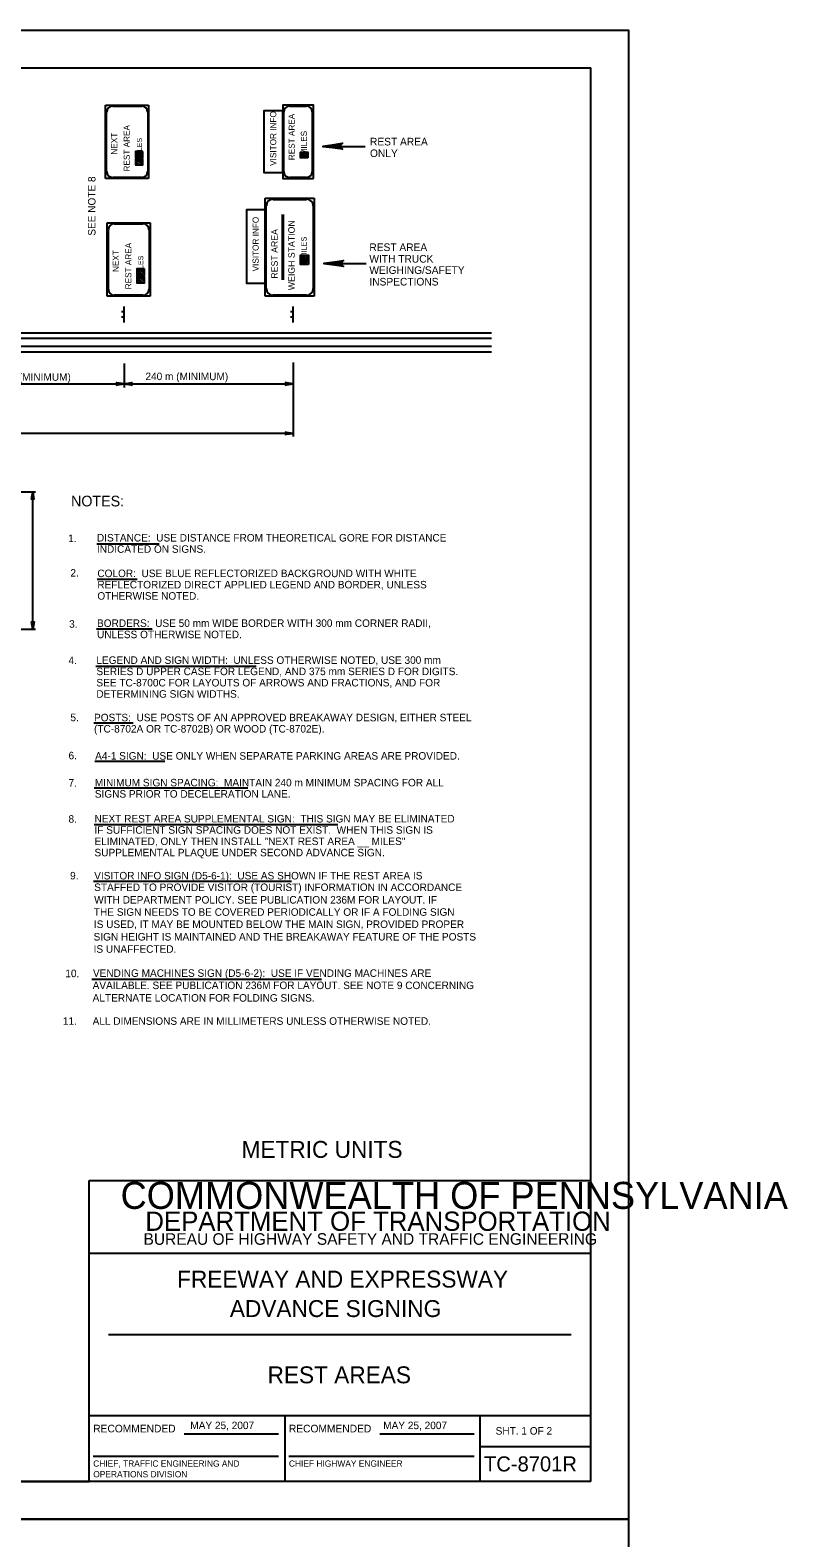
# Model space of a CAD drawing. Extents: x 649604 to 650509, y 298458 to 299646.
# Drawn here: x 650207 to 650509, y 299044 to 299646 of the extents above; entities that cross this region are included whole.
import ezdxf

# ---------------------------------------------------------------- set-up
doc = ezdxf.new("R2010")
doc.units = 0
for name, color, linetype in [('1', 7, 'Continuous'), ('2', 7, 'Continuous'), ('3', 7, 'Continuous'), ('PLT-BNDY', 7, 'Continuous')]:
    doc.layers.add(name, color=color, linetype=linetype)

# ---------------------------------------------------------------- blocks, each defined once
blk = doc.blocks.new('RARROW')
at = {"layer": '3'}
blk.add_lwpolyline([(-2.2695, 0.285), (-2.184875, 0.12075), (0, 0), (-2.2695, 0.285), (-2.38575, 0.384625), (0, 0), (-2.183125, -0.108), (-2.262875, -0.2705), (0, 0), (-2.38575, -0.379125), (-2.262875, -0.2705)], dxfattribs=at)

msp = doc.modelspace()

# ---------------------------------------------------------------- linework, layer by layer
at = {"layer": '1'}
for p, q in [((649644.31, 299630.63), (650430.31, 299630.63)), ((650430.31, 299066.63), (650430.31, 299630.63)), ((650230.31, 299066.63), (650230.31, 299186.63)), ((650230.31, 299186.63), (650430.31, 299186.63)), ((650430.31, 299157.63), (650230.31, 299157.63)), ((650238.06, 299125.31), (650422.56, 299125.31)), ((650230.31, 299093), (650430.31, 299093)), ((650308.31, 299093), (650308.31, 299066.63)), ((650386.19, 299066.63), (650386.19, 299093)), ((650268.24, 299085.57), (650305.87, 299085.57)), ((650346.24, 299085.57), (650383.87, 299085.57)), ((650386.19, 299080.63), (650430.31, 299080.63)), ((650231.99, 299076.68), (650305.87, 299076.68)), ((650309.99, 299076.68), (650383.87, 299076.68)), ((650430.31, 299066.63), (649644.31, 299066.63)), ((649644.31, 299066.63), (650230.31, 299066.63))]:
    msp.add_line(p, q, dxfattribs=at)
at = {"layer": '2'}
for p, q in [((650236.94, 299586.5), (650236.94, 299615.75)), ((650236.94, 299615.75), (650254.06, 299615.75)), ((650239.81, 299615.25), (650251.31, 299615.25)), ((650254.06, 299615.75), (650254.06, 299586.5)), ((650310.31, 299615.25), (650316.94, 299615.25)), ((650237.31, 299589.25), (650237.31, 299612.88)), ((650253.69, 299612.88), (650253.69, 299589.25)), ((650323.56, 299599.25), (650340.44, 299599.25)), ((650254.06, 299586.5), (650236.94, 299586.5)), ((650251.31, 299586.88), (650239.81, 299586.88)), ((650300.56, 299539.5), (650300.56, 299578.63)), ((650303.56, 299578.13), (650317.06, 299578.13)), ((650320.06, 299578.63), (650320.06, 299539.5)), ((650300.94, 299542.5), (650300.94, 299575.63)), ((650307.44, 299546), (650307.44, 299572.13)), ((650307.56, 299546), (650307.56, 299572.13)), ((650307.69, 299546), (650307.69, 299572.13)), ((650307.81, 299546), (650307.81, 299572.13)), ((650307.81, 299546), (650307.81, 299572.13)), ((650319.69, 299575.63), (650319.69, 299542.5)), ((650237.56, 299539.5), (650237.56, 299568.75)), ((650237.56, 299568.75), (650254.69, 299568.75)), ((650238.06, 299542.25), (650238.06, 299565.88)), ((650240.31, 299568.38), (650251.81, 299568.38)), ((650254.31, 299565.88), (650254.31, 299542.25)), ((650254.69, 299568.75), (650254.69, 299539.5)), ((650323.94, 299552.5), (650340.81, 299552.5)), ((650254.69, 299539.5), (650237.56, 299539.5)), ((650251.81, 299539.88), (650240.31, 299539.88)), ((650244.31, 299529), (650244.31, 299535.38)), ((650311.69, 299529), (650311.69, 299535.38)), ((650244.31, 299533.25), (650243.31, 299533.25)), ((650244.31, 299531.13), (650243.31, 299531.13)), ((650311.69, 299533.25), (650310.56, 299533.25)), ((650311.69, 299531.13), (650310.56, 299531.13)), ((649946.56, 299524.88), (650390.69, 299524.88)), ((650330.44, 299524.88), (650330.44, 299524.88)), ((649664.19, 299522.75), (650390.69, 299522.75)), ((649664.19, 299519.5), (650390.69, 299519.5)), ((649664.19, 299517.25), (650390.69, 299517.25)), ((650244.31, 299512.63), (650244.31, 299503)), ((650311.69, 299513), (650311.69, 299483.5)), ((650176.94, 299504.5), (650244.31, 299504.5)), ((650244.31, 299504.5), (650311.69, 299504.5)), ((650311.69, 299484.75), (649881.31, 299484.75)), ((650180.48, 299461.5), (650209, 299461.5)), ((650207.88, 299406.63), (650207.88, 299461.5)), ((650233.42, 299440.75), (650258.31, 299440.75)), ((650233.57, 299426.66), (650249.5, 299426.66)), ((650180.48, 299406.63), (650209, 299406.63)), ((650233.32, 299406.8), (650255.5, 299406.8)), ((650232.96, 299391.93), (650297, 299391.93)), ((650232.22, 299369.29), (650247.93, 299369.29)), ((650232.57, 299353.98), (650260.48, 299353.98)), ((650232.31, 299343.4), (650293.65, 299343.4)), ((650232.3, 299328.76), (650329.5, 299328.76)), ((650232.07, 299306.17), (650311.03, 299306.17)), ((650231.47, 299267.05), (650322.98, 299267.05))]:
    msp.add_line(p, q, dxfattribs=at)
for points in [[(650307.56, 299588.88), (650307.56, 299613.38), (650299.94, 299613.38), (650299.94, 299588.88)], [(650319.81, 299586.5), (650319.81, 299615.75), (650307.56, 299615.75), (650307.56, 299586.5)], [(650251.81, 299597.25), (650248.81, 299597.25), (650248.81, 299594.88), (650251.81, 299594.88)], [(650317.56, 299594.75), (650314.56, 299594.75), (650314.56, 299597), (650317.56, 299597)], [(650251.81, 299594.25), (650248.81, 299594.25), (650248.81, 299591.88), (650251.81, 299591.88)], [(650300.56, 299544.63), (650300.56, 299574), (650293.06, 299574), (650293.06, 299544.63)], [(650317.81, 299552.13), (650314.56, 299552.13), (650314.56, 299555.88), (650317.81, 299555.88)], [(650252.44, 299550.38), (650249.31, 299550.38), (650249.31, 299547.88), (650252.44, 299547.88)], [(650252.44, 299547.38), (650249.31, 299547.38), (650249.31, 299544.88), (650252.44, 299544.88)]]:
    msp.add_lwpolyline(points, close=True, dxfattribs=at)
for points in [[(650307.94, 299589.25), (650307.94, 299612.88)], [(650319.31, 299612.88), (650319.31, 299589.25)], [(650251.31, 299594.88), (650248.81, 299597.25)], [(650250.31, 299594.88), (650248.81, 299596.5)], [(650249.44, 299594.88), (650248.81, 299595.75)], [(650251.81, 299595.13), (650249.69, 299597.25)], [(650251.81, 299596), (650250.44, 299597.25)], [(650251.81, 299597), (650251.44, 299597.25)], [(650316.81, 299594.75), (650314.56, 299597)], [(650316.31, 299594.75), (650314.56, 299596.5)], [(650315.81, 299594.75), (650314.56, 299596)], [(650315.44, 299594.75), (650314.56, 299595.63)], [(650314.94, 299594.75), (650314.56, 299595.13)], [(650317.19, 299594.75), (650314.81, 299597)], [(650317.56, 299594.88), (650315.19, 299597)], [(650317.56, 299595.38), (650315.69, 299597)], [(650317.56, 299595.88), (650316.19, 299597)], [(650317.56, 299596.25), (650316.69, 299597)], [(650317.56, 299596.75), (650317.06, 299597)], [(650331.06, 299598.38), (650330.69, 299599), (650323.56, 299599.25), (650331.06, 299598.38), (650331.31, 299598.13), (650323.56, 299599.25), (650330.69, 299599.75), (650330.94, 299600.25), (650323.56, 299599.25), (650331.31, 299600.5), (650330.94, 299600.25)], [(650251.31, 299591.88), (650248.81, 299594.25)], [(650250.31, 299591.88), (650248.81, 299593.5)], [(650249.44, 299591.88), (650248.81, 299592.5)], [(650251.81, 299592.13), (650249.56, 299594.25)], [(650251.81, 299592.88), (650250.44, 299594.25)], [(650251.81, 299593.88), (650251.44, 299594.25)], [(650316.94, 299586.88), (650310.31, 299586.88)], [(650300.56, 299578.63), (650302.94, 299578.63), (650305.56, 299578.63), (650307.69, 299578.63), (650309.69, 299578.63), (650312.31, 299578.63), (650314.56, 299578.63), (650315.06, 299578.63), (650317.06, 299578.63), (650317.81, 299578.63), (650320.06, 299578.63)], [(650317.81, 299552.75), (650314.56, 299555.88)], [(650317.31, 299552.13), (650314.56, 299555.13)], [(650316.44, 299552.13), (650314.56, 299554.13)], [(650315.56, 299552.13), (650314.56, 299553.25)], [(650317.81, 299553.63), (650315.44, 299555.88)], [(650317.81, 299554.5), (650316.44, 299555.88)], [(650317.81, 299555.5), (650317.31, 299555.88)], [(650331.31, 299551.63), (650331.19, 299552.13), (650323.94, 299552.5), (650331.31, 299551.63), (650331.69, 299551.38), (650323.94, 299552.5), (650331.19, 299553), (650331.31, 299553.5), (650323.94, 299552.5), (650331.69, 299553.75), (650331.31, 299553.5)], [(650251.81, 299547.88), (650249.31, 299550.38)], [(650251.06, 299547.88), (650249.31, 299549.5)], [(650250.19, 299547.88), (650249.31, 299548.75)], [(650251.81, 299544.88), (650249.31, 299547.38)], [(650252.44, 299548.25), (650250.31, 299550.38)], [(650252.44, 299545.25), (650250.31, 299547.38)], [(650252.44, 299549.13), (650251.19, 299550.38)], [(650252.44, 299546), (650251.19, 299547.38)], [(650252.44, 299549.88), (650252.06, 299550.38)], [(650252.44, 299546.88), (650252.06, 299547.38)], [(650314.56, 299552.13), (650314.56, 299552.25)], [(650251.06, 299544.88), (650249.31, 299546.5)], [(650250.19, 299544.88), (650249.31, 299545.5)], [(650320.06, 299539.5), (650300.56, 299539.5)], [(650317.06, 299539.88), (650303.56, 299539.88)]]:
    msp.add_lwpolyline(points, dxfattribs=at)
for centre, radius, start, end in [((650239.81, 299612.91), 2.44, 90, 180), ((650251.22, 299612.91), 2.44, 0, 90), ((650310.4, 299612.91), 2.44, 90, 180), ((650316.92, 299612.91), 2.44, 0, 90), ((650239.81, 299589.29), 2.44, 180, 270), ((650251.22, 299589.29), 2.44, 270, 0), ((650310.4, 299589.29), 2.44, 180, 270), ((650316.92, 299589.29), 2.44, 270, 0), ((650303.6, 299575.54), 2.61, 90, 180), ((650317.08, 299575.54), 2.61, 0, 90), ((650240.41, 299565.93), 2.44, 90, 180), ((650251.82, 299565.93), 2.44, 0, 90), ((650240.41, 299542.3), 2.44, 180, 270), ((650251.82, 299542.3), 2.44, 270, 0), ((650303.6, 299542.5), 2.61, 180, 270), ((650317.08, 299542.5), 2.61, 270, 0)]:
    msp.add_arc(centre, radius, start, end, dxfattribs=at)
at = {"layer": 'PLT-BNDY'}
for points in [[(649604.31, 299645.63), (650445.31, 299645.63), (650445.31, 299051.63), (649604.31, 299051.63)], [(649604.31, 299051.63), (650445.31, 299051.63), (650445.31, 298457.63), (649604.31, 298457.63)]]:
    msp.add_lwpolyline(points, close=True, dxfattribs=at)

# ---------------------------------------------------------------- block references
at = {"layer": '2', "xscale": 1.2574347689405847, "yscale": 1.3092961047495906}
for p in [(650244.31, 299504.5), (650311.69, 299504.5), (650311.69, 299484.75)]:
    msp.add_blockref('RARROW', p, dxfattribs=at)
for p, rotation in [((650244.31, 299504.5), 180), ((650207.88, 299461.5), 89.99999999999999), ((650207.88, 299406.63), -90.00000000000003)]:
    msp.add_blockref('RARROW', p, dxfattribs=dict(at, rotation=rotation))

# ---------------------------------------------------------------- texts
at = {"layer": '1'}
for s, height, p in [('COMMONWEALTH OF PENNSYLVANIA', 10.7828, (650242.9, 299175.36)), ('DEPARTMENT OF TRANSPORTATION', 7.6837, (650252.76, 299166.61)), ('BUREAU OF HIGHWAY SAFETY AND TRAFFIC ENGINEERING', 4.6253, (650252.04, 299161.04)), ('FREEWAY AND EXPRESSWAY', 6.75, (650265.42, 299143.97)), ('ADVANCE SIGNING', 6.75, (650286.45, 299132.22)), ('REST AREAS', 6.75, (650301.47, 299105.78)), ('RECOMMENDED', 3.048, (650231.99, 299086.2)), ('RECOMMENDED', 3.048, (650309.99, 299086.2)), ('SHT. 1 OF 2', 3, (650392.4, 299085.31)), ('CHIEF, TRAFFIC ENGINEERING AND', 2.5, (650231.99, 299072.51)), ('CHIEF HIGHWAY ENGINEER', 2.5, (650309.99, 299072.51)), ('TC-8701R', 6, (650387.77, 299070.63)), ('OPERATIONS DIVISION', 2.5, (650231.99, 299068.26))]:
    msp.add_text(s, height=height, dxfattribs=at).set_placement(p)
at = {"layer": '2'}
for s, height, p in [('REST AREA', 2.443, (650246.56, 299589.25)), ('VISITOR INFO', 2.4443, (650304.94, 299591.5)), ('REST AREA', 2.444, (650312.31, 299593.75)), ('NEXT', 2.443, (650241.56, 299596)), ('   MILES', 2.035, (650251.44, 299591.88)), ('    MILES', 2.443, (650317.19, 299592)), ('SEE NOTE 8', 3, (650232.89, 299563.63)), ('VISITOR INFO', 2.4443, (650297.94, 299549.38)), ('REST AREA', 2.608, (650305.56, 299546.5)), ('WEIGH STATION', 2.6078, (650312.31, 299541.88)), ('REST AREA', 2.443, (650247.19, 299542.25)), ('  MILES', 2.174, (650317.06, 299552.63)), ('NEXT', 2.443, (650242.19, 299549.13)), ('   MILES', 2.035, (650251.94, 299544.88))]:
    msp.add_text(s, height=height, rotation=90, dxfattribs=at).set_placement(p)
for s, height, p in [('REST AREA', 3.041, (650342.31, 299599.63)), ('ONLY', 3.041, (650342.31, 299595)), ('REST AREA', 3.041, (650342.06, 299557.5)), ('WITH TRUCK', 3.041, (650342.06, 299552.88)), ('WEIGHING/SAFETY', 3.0405, (650342.06, 299548.38)), ('INSPECTIONS', 3.0405, (650342.06, 299543.75)), ('240 m (MINIMUM)', 3, (650190.06, 299505.75)), ('240 m (MINIMUM)', 3, (650252.81, 299506)), ('NOTES:', 4.25, (650223.15, 299455.63)), ('1.  ', 3, (650222, 299441.41)), ('DISTANCE:  USE DISTANCE FROM THEORETICAL GORE FOR DISTANCE', 3, (650233.47, 299441.62)), ('INDICATED ON SIGNS.', 3, (650233.47, 299437.12)), ('2.  ', 3, (650222.89, 299427.61)), ('COLOR:  USE BLUE REFLECTORIZED BACKGROUND WITH WHITE', 3, (650233.63, 299427.41)), ('OTHERWISE NOTED.', 3, (650233.63, 299418.41)), ('REFLECTORIZED DIRECT APPLIED LEGEND AND BORDER, UNLESS', 3, (650233.63, 299422.91)), ('3.  ', 3, (650222.38, 299407.21)), ('BORDERS:  USE 50 mm WIDE BORDER WITH 300 mm CORNER RADII,', 3, (650233.5, 299407.55)), ('UNLESS OTHERWISE NOTED.', 3, (650233.5, 299403.05)), ('4.', 3, (650222.13, 299392.69)), ('SERIES D UPPER CASE FOR LEGEND, AND 375 mm SERIES D FOR DIGITS.', 3, (650233.25, 299388.3)), ('LEGEND AND SIGN WIDTH:  UNLESS OTHERWISE NOTED, USE 300 mm', 3, (650233.25, 299392.8)), ('SEE TC-8700C FOR LAYOUTS OF ARROWS AND FRACTIONS, AND FOR ', 3, (650233.25, 299383.8)), ('DETERMINING SIGN WIDTHS.', 3, (650233.25, 299379.3)), ('5.  ', 3, (650222.89, 299369.93)), ('POSTS:  USE POSTS OF AN APPROVED BREAKAWAY DESIGN, EITHER STEEL', 3, (650232.31, 299369.9)), ('(TC-8702A OR TC-8702B) OR WOOD (TC-8702E).', 3, (650232.31, 299365.4)), ('6.  ', 3, (650222.14, 299354.74)), ('A4-1 SIGN:  USE ONLY WHEN SEPARATE PARKING AREAS ARE PROVIDED.', 3, (650232.75, 299354.6)), ('7.  ', 3, (650222.12, 299343.81)), ('MINIMUM SIGN SPACING:  MAINTAIN 240 m MINIMUM SPACING FOR ALL', 3, (650232.63, 299343.93)), ('SIGNS PRIOR TO DECELERATION LANE.', 3, (650232.63, 299339.43)), ('8.  ', 3, (650222.13, 299329.43)), ('NEXT REST AREA SUPPLEMENTAL SIGN:  THIS SIGN MAY BE ELIMINATED', 3, (650232.5, 299329.53)), ('IF SUFFICIENT SIGN SPACING DOES NOT EXIST.  WHEN THIS SIGN IS', 3, (650232.5, 299325.03)), ('SUPPLEMENTAL PLAQUE UNDER SECOND ADVANCE SIGN.', 3, (650232.5, 299316.03)), ('ELIMINATED, ONLY THEN INSTALL "NEXT REST AREA __ MILES" ', 3, (650232.5, 299320.53)), ('9.  ', 3, (650222.76, 299306.81)), ('VISITOR INFO SIGN (D5-6-1):  USE AS SHOWN IF THE REST AREA IS', 3, (650232.38, 299306.8)), ('STAFFED TO PROVIDE VISITOR (TOURIST) INFORMATION IN ACCORDANCE', 3, (650232.38, 299302.18)), ('THE SIGN NEEDS TO BE COVERED PERIODICALLY OR IF A FOLDING SIGN', 3, (650232.25, 299292.3)), ('WITH DEPARTMENT POLICY. SEE PUBLICATION 236M FOR LAYOUT. IF', 3, (650232.38, 299297.17)), ('IS USED, IT MAY BE MOUNTED BELOW THE MAIN SIGN, PROVIDED PROPER', 3, (650232.25, 299287.43)), ('SIGN HEIGHT IS MAINTAINED AND THE BREAKAWAY FEATURE OF THE POSTS', 3, (650232.13, 299282.43)), ('IS UNAFFECTED.', 3, (650232.13, 299277.55)), ('10.   ', 3, (650220.87, 299267.81)), ('VENDING MACHINES SIGN (D5-6-2):  USE IF VENDING MACHINES ARE', 3, (650231.88, 299267.93)), ('AVAILABLE. SEE PUBLICATION 236M FOR LAYOUT. SEE NOTE 9 CONCERNING', 3, (650231.75, 299263.05)), ('ALTERNATE LOCATION FOR FOLDING SIGNS.', 3, (650231.75, 299258.05)), ('11. ', 3, (650219.88, 299248.8)), ('ALL DIMENSIONS ARE IN MILLIMETERS UNLESS OTHERWISE NOTED.', 3, (650231.75, 299248.8)), ('METRIC UNITS', 6.75, (650291.11, 299195.72)), ('MAY 25, 2007', 3, (650270.69, 299087.49)), ('MAY 25, 2007', 3, (650347.59, 299087.49))]:
    msp.add_text(s, height=height, dxfattribs=at).set_placement(p)

doc.saveas('drawing.dxf')
